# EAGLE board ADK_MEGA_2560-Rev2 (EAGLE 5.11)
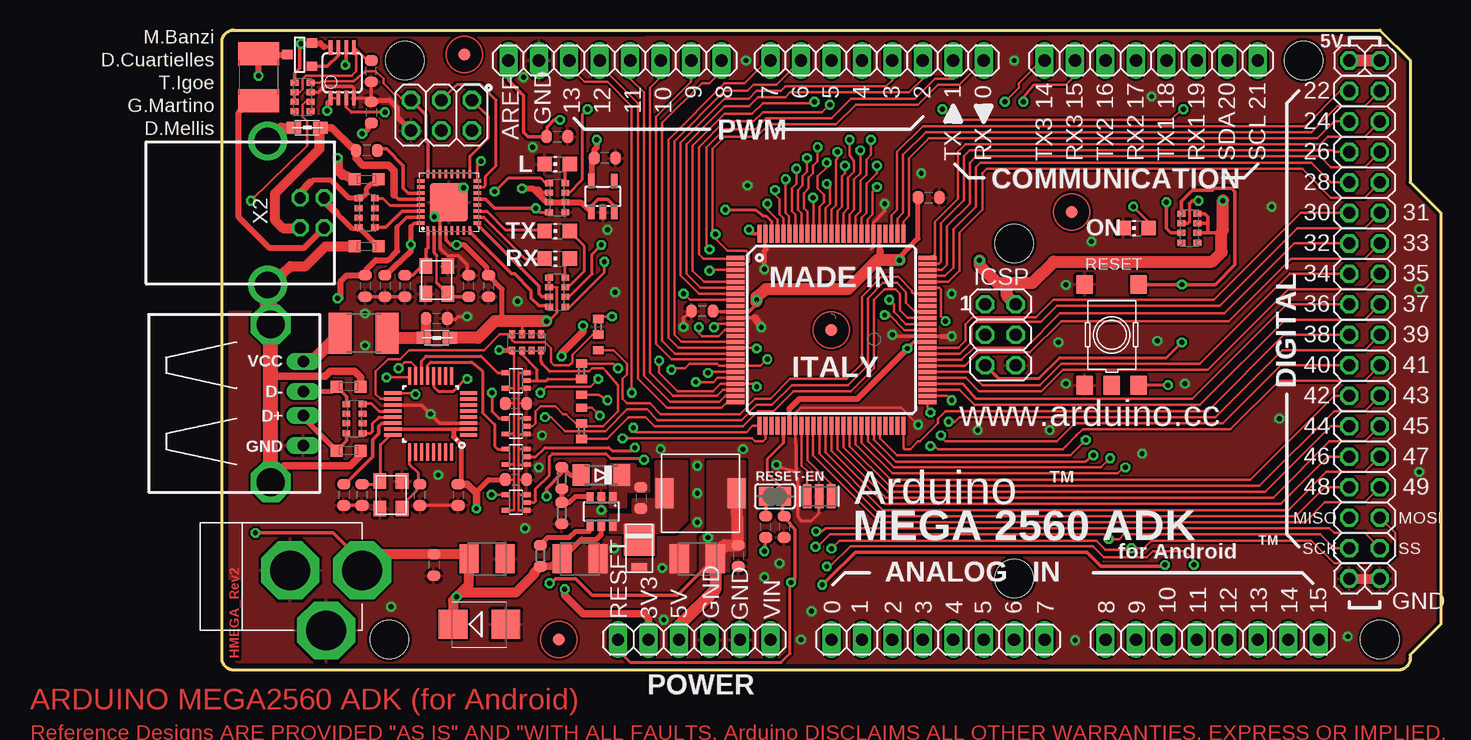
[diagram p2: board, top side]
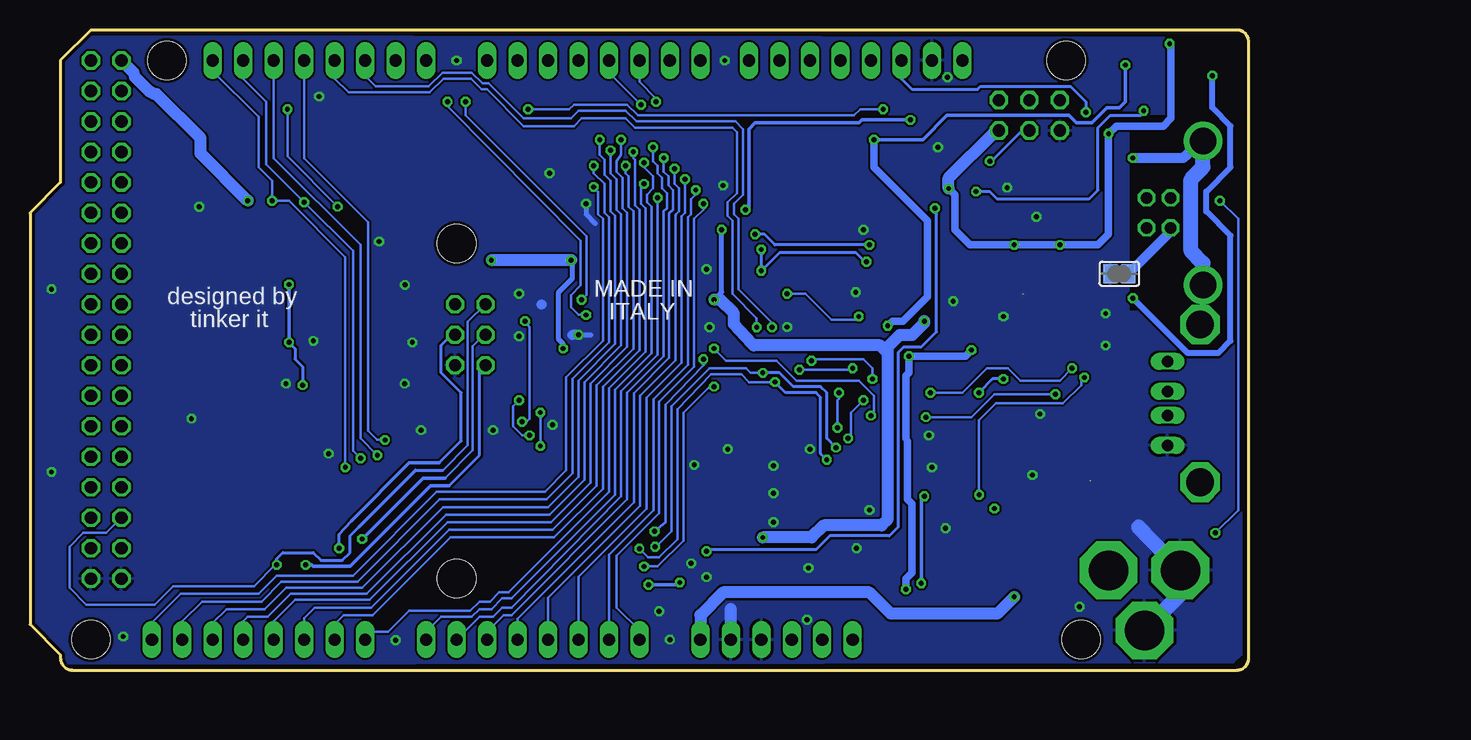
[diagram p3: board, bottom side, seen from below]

Size 101.6 x 53.34 mm. Coordinates in mm from the lower left corner, seen from the top.
Outline: 96.52,53.34 99.06,50.8 99.06,40.64 101.6,38.1 101.6,3.81 99.06,1.27 99.06,1 arc-90 98.06,0 1,0 arc-90 0,1 0,52.34 arc-90 1,53.34 96.52,53.34
Copper layers (1*16): Top 0.035mm / dielectric 1.5mm / Bottom 0.035mm
Design rules "ArduinoDEF": minimum track width 6mil, minimum drill 12mil, track to track 5mil, track to pad 5mil, pad to pad 5mil, via to via 5mil, smd to smd 4mil, copper to edge 10mil, drill to drill 6mil, minimum pad ring 8mil, minimum via ring 8mil, stop-mask expansion 0mil, vias tented up to drill 0mil, thermal gap 10mil
Net classes: 0 default: width 0.203 mm, drill 0.406 mm, clearance 0.178 mm; 1 power: width 0.305 mm, drill 0.406 mm, clearance 0.178 mm; 2 gnd: width 0.305 mm, drill 0.406 mm, clearance 0.178 mm; 3 power usb: width 0.508 mm, drill 0.406 mm, clearance 0.178 mm
Holes 3.2 mm at 96.52,2.54 15.24,50.8 90.17,50.8 13.97,2.54 66.04,35.56 66.04,7.62

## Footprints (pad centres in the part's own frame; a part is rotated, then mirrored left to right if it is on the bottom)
1X08 = drill 1.016 long: 1 -8.89,0; 2 -6.35,0; 3 -3.81,0; 4 -1.27,0; 5 1.27,0; 6 3.81,0; 7 6.35,0; 8 8.89,0
C0603-ROUND = smd 0.898 x 1.1: 1 -0.889,0; 2 0.889,0
SMC_B = smd 1.6 x 2.4: + -1.5,0; - 1.5,0
MINIMELF = smd 1.4 x 1.8: A 1.7,0; C -1.7,0
SMB = smd 2.4 x 2.4: A 2.2,0; C -2.2,0
DO220AAL = smd 2.667 x 2.54: P$1 -0.7,0 | smd 0.762 x 1.27: P$2 1.65,0
L1812 = smd 1.9 x 3.4: 1 -1.95,0; 2 1.95,0
SJ = smd 1.168 x 1.6: 1 -0.762,0; 2 0.762,0
MSOP08 = smd 0.3 x 1.2: 1 -0.976,-2.113; 2 -0.326,-2.113; 3 0.324,-2.113; 4 0.974,-2.113; 5 0.974,2.112; 6 0.324,2.112; 7 -0.326,2.112; 8 -0.976,2.112
SOT23-6 = smd 0.6 x 0.9: 1 -0.95,-1.15; 2 0,-1.15; 3 0.95,-1.15; 4 0.95,1.15; 5 0,1.15; 6 -0.95,1.15
TQFP100 = smd 1.5 x 0.35: 1 -8,6; 2 -8,5.5; 3 -8,5; 4 -8,4.5; 5 -8,4; 6 -8,3.5; 7 -8,3; 8 -8,2.5; 9 -8,2; 10 -8,1.5; 11 -8,1; 12 -8,0.5; 13 -8,0; 14 -8,-0.5; 15 -8,-1; 16 -8,-1.5; 17 -8,-2; 18 -8,-2.5; 19 -8,-3; 20 -8,-3.5; 21 -8,-4; 22 -8,-4.5; 23 -8,-5; 24 -8,-5.5; 25 -8,-6; 51 8,-6; 52 8,-5.5; 53 8,-5; 54 8,-4.5; 55 8,-4; 56 8,-3.5; 57 8,-3; 58 8,-2.5; 59 8,-2; 60 8,-1.5; 61 8,-1; 62 8,-0.5; 63 8,0; 64 8,0.5; 65 8,1; 66 8,1.5; 67 8,2; 68 8,2.5; 69 8,3; 70 8,3.5; 71 8,4; 72 8,4.5; 73 8,5; 74 8,5.5; 75 8,6 | smd 0.35 x 1.5: 26 -6,-8; 27 -5.5,-8; 28 -5,-8; 29 -4.5,-8; 30 -4,-8; 31 -3.5,-8; 32 -3,-8; 33 -2.5,-8; 34 -2,-8; 35 -1.5,-8; 36 -1,-8; 37 -0.5,-8; 38 0,-8; 39 0.5,-8; 40 1,-8; 41 1.5,-8; 42 2,-8; 43 2.5,-8; 44 3,-8; 45 3.5,-8; 46 4,-8; 47 4.5,-8; 48 5,-8; 49 5.5,-8; 50 6,-8; 76 6,8; 77 5.5,8; 78 5,8; 79 4.5,8; 80 4,8; 81 3.5,8; 82 3,8; 83 2.5,8; 84 2,8; 85 1.5,8; 86 1,8; 87 0.5,8; 88 0,8; 89 -0.5,8; 90 -1,8; 91 -1.5,8; 92 -2,8; 93 -2.5,8; 94 -3,8; 95 -3.5,8; 96 -4,8; 97 -4.5,8; 98 -5,8; 99 -5.5,8; 100 -6,8
ATMEL_QFN32 = smd 0.711 x 0.305: 1 -2.351,1.75; 2 -2.351,1.25; 3 -2.351,0.75; 4 -2.351,0.25; 5 -2.351,-0.25; 6 -2.351,-0.75; 7 -2.351,-1.25; 8 -2.351,-1.75; 17 2.351,-1.75; 18 2.351,-1.25; 19 2.351,-0.75; 20 2.351,-0.25; 21 2.351,0.25; 22 2.351,0.75; 23 2.351,1.25; 24 2.351,1.75 | smd 0.305 x 0.711: 9 -1.75,-2.351; 10 -1.25,-2.351; 11 -0.75,-2.351; 12 -0.25,-2.351; 13 0.25,-2.351; 14 0.75,-2.351; 15 1.25,-2.351; 16 1.75,-2.351; 25 1.75,2.351; 26 1.25,2.351; 27 0.75,2.351; 28 0.25,2.351; 29 -0.25,2.351; 30 -0.75,2.351; 31 -1.25,2.351; 32 -1.75,2.351 | smd 3.2 x 3.2: EXP 0,0
SC70-5 = smd 0.4 x 0.7: 1 -0.65,-0.85; 2 0,-0.85; 3 0.65,-0.85; 4 0.65,0.85; 5 -0.65,0.85
SOT23-DBV = smd 0.55 x 1.2: 1 -0.95,-1.3; 2 0,-1.3; 3 0.95,-1.3; 4 0.95,1.3; 5 -0.95,1.3
2X03 = drill 1.016 octagon: 1 -2.54,-1.27; 2 -2.54,1.27; 3 0,-1.27; 4 0,1.27; 5 2.54,-1.27; 6 2.54,1.27
1X01 = drill 1.016 octagon: 1 0,0
CHIP-LED0805 = smd 1.2 x 1.2: A 0,-1.05; C 0,1.05
SRR0604 = smd 1.5 x 2.5: P$1 3,0; P$2 -3,0
0805 = smd 1.2 x 1: 1 -1.1,0; 2 1.1,0
PN87520 = drill 0.95 long: 1 -3.5,2.71; 2 -1,2.71; 3 1,2.71; 4 3.5,2.71 | drill 2.3 octagon: SG1 -6.57,0; SG2 6.57,0
1X06 = drill 1.016 long: 1 -6.35,0; 2 -3.81,0; 3 -1.27,0; 4 1.27,0; 5 3.81,0; 6 6.35,0
R0603-ROUND = smd 0.898 x 1.1: 1 -0.889,0; 2 0.889,0
J0402 = smd 0.7 x 0.9: 1 -0.65,0; 2 0.65,0; 3 1.95,0
R0402 = smd 0.7 x 0.9: 1 -0.65,0; 2 0.65,0
TS42 = smd 1.6 x 1.4: 1 -4.2,2.25; 2 4.2,2.25; 3 -4.2,-2.25; 4 4.2,-2.25; 5 -4.2,0
CAT16 = smd 0.5 x 0.65: 1 -1.2,-0.675; 2 -0.4,-0.675; 3 0.4,-0.675; 4 1.2,-0.675; 5 1.2,0.675; 6 0.4,0.675; 7 -0.4,0.675; 8 -1.2,0.675
CAY16 = smd 0.5 x 0.65: 1 -1.2,-0.675; 2 -0.4,-0.675; 3 0.4,-0.675; 4 1.2,-0.675; 5 1.2,0.675; 6 0.4,0.675; 7 -0.4,0.675; 8 -1.2,0.675
SOT-23 = smd 0.787 x 0.889: 1 0.025,-1.016; 2 -0.94,1.016; 3 0.991,1.016
TQFP32-05 = smd 0.27 x 1.45: 1 -1.75,-3.16; 2 -1.25,-3.16; 3 -0.75,-3.16; 4 -0.25,-3.16; 5 0.25,-3.16; 6 0.75,-3.16; 7 1.25,-3.16; 8 1.75,-3.16; 17 1.75,3.16; 18 1.25,3.16; 19 0.75,3.16; 20 0.25,3.16; 21 -0.25,3.16; 22 -0.75,3.16; 23 -1.25,3.16; 24 -1.75,3.16 | smd 1.45 x 0.27: 9 3.16,-1.75; 10 3.16,-1.25; 11 3.16,-0.75; 12 3.16,-0.25; 13 3.16,0.25; 14 3.16,0.75; 15 3.16,1.25; 16 3.16,1.75; 25 -3.16,1.75; 26 -3.16,1.25; 27 -3.16,0.75; 28 -3.16,0.25; 29 -3.16,-0.25; 30 -3.16,-0.75; 31 -3.16,-1.25; 32 -3.16,-1.75
FIDUCIA-MOUNT = smd 1.016 x 1.016: P$1 0,0
DC-21MM = drill 3.302 pad 4.826 octagon: 1 -5.08,-3.353; 2 -0.076,-6.35; 3 -0.076,-0.356
PN61729 = drill 0.95 octagon: 1 1.25,4.71; 2 -1.25,4.71; 3 -1.25,2.71; 4 1.25,2.71 | drill 2.2 round: P$1 -6,0; P$2 6,0
2X08 = drill 1.016 octagon: 1 -8.89,-1.27; 2 -8.89,1.27; 3 -6.35,-1.27; 4 -6.35,1.27; 5 -3.81,-1.27; 6 -3.81,1.27; 7 -1.27,-1.27; 8 -1.27,1.27; 9 1.27,-1.27; 10 1.27,1.27; 11 3.81,-1.27; 12 3.81,1.27; 13 6.35,-1.27; 14 6.35,1.27; 15 8.89,-1.27; 16 8.89,1.27
RESONATOR = smd 0.7 x 2: 1 -1,0; 2 0,0; 3 1,0
CRYSTAL-3.2-2.5 = smd 1.3 x 1.05: 1 -1.15,-0.925; 2 1.15,-0.925; 3 1.15,0.925; 4 -1.15,0.925
CT/CN0603 = smd 1 x 1: 1 -1,0; 2 1,0

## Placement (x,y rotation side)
ADCH  [1X08]  82.55,2.54 0 top
ADCL  [1X08]  59.69,2.54 0 top
C1  22p  [C0603-ROUND]  46.86,11.94 270 top
C2  10n  [C0603-ROUND]  34.92,14.35 270 top
C3  100n  [C0603-ROUND]  17.65,8.76 270 top
C4  10u  [SMC_B]  29.84,9.27 0 top
C5  10u  [SMC_B]  39.62,9.27 180 top
C6  100n  [C0603-ROUND]  27.94,44.45 0 top
C7  100n  [C0603-ROUND]  43.05,9.53 270 top
C8  100n  [C0603-ROUND]  58.93,39.37 0 top
C9  100n  [C0603-ROUND]  40.05,29.91 180 top
C10  100n  [C0603-ROUND]  45.34,11.94 90 top
C11  100n  [C0603-ROUND]  11.94,32 270 top
C12  22p  [C0603-ROUND]  20.57,32 90 top
C13  22p  [C0603-ROUND]  15.24,32 270 top
C14  100n  [C0603-ROUND]  22.23,32 270 top
C15  100n  [C0603-ROUND]  13.59,32 270 top
C16  1u  [C0603-ROUND]  12.06,43.31 180 top
C17  100n  [C0603-ROUND]  17.91,29.31 0 top
C18  100n  [C0603-ROUND]  19.68,14.61 270 top
C19  22p  [C0603-ROUND]  16.51,14.61 90 top
C20  22p  [C0603-ROUND]  11.68,14.61 90 top
C21  100n  [C0603-ROUND]  12.45,46.48 270 top
C22  100n  [C0603-ROUND]  12.45,49.91 90 top
C23  1u  [C0603-ROUND]  31.93,42.67 180 top
C24  100n  [C0603-ROUND]  10.16,14.61 270 top
C25  100n  [C0603-ROUND]  24.51,22.23 0 top
C26  100n  [C0603-ROUND]  24.51,15.88 0 top
COMMUNICATION  [1X08]  77.47,50.8 180 top
D1  4148  [MINIMELF]  31.62,16.26 180 top
D2  M7  [SMB]  21.46,3.81 0 top
D3  SS1P3L  [DO220AAL]  34.8,10.16 270 top
F1  500mA  [L1812]  3.05,49.4 270 top
F2  500mA  [L1812]  11.81,28.07 180 top
GROUND  [SJ]  10.79,33.02 180 bottom
IC1  LMV358MMX  [MSOP08]  10.03,49.78 0 top
IC2  LM2736Y  [SOT23-6]  31.62,13.21 180 top
IC3  ATMEGA2560-16AU  [TQFP100]  50.8,28.35 0 top
IC4  ATMEGA8U2-MU  [ATMEL_QFN32]  18.92,38.99 90 top
IC5  74LVC1G125DCK  [SC70-5]  24.51,20.32 90 top
IC6  74LVC1G125DCK  [SC70-5]  24.51,17.78 90 top
IC7  LP2985-33DBVR  [SOT23-DBV]  31.75,39.47 0 top
IC8  74LVC1G125DCK  [SC70-5]  24.51,24.13 90 top
IC9  74LVC1G125DCK  [SC70-5]  24.51,13.97 90 top
ICSP  ICSP  [2X03]  64.9,27.94 270 top
ICSP1  ICSP  [2X03]  18.29,46.23 180 top
JP1  [1X01]  93.98,50.8 0 top
JP2  [1X01]  96.52,50.8 0 top
JP3  [1X01]  93.98,7.62 0 top
JP4  [1X01]  96.52,7.62 0 top
L  YELLOW  [CHIP-LED0805]  27.94,42.16 90 top
L1  4u7  [SRR0604]  39.88,14.73 180 top
L2  BLM21  [0805]  7.11,45.21 180 top
L3  BLM21  [0805]  17.91,27.69 180 top
ON  GREEN  [CHIP-LED0805]  76.2,36.83 90 top
PC1  47u  [SMC_B]  22.1,9.27 0 top
PHONE  [PN87520]  4.06,22.23 270 top
POWER  [1X06]  39.37,2.54 0 top
PWMH  [1X08]  32.77,50.8 180 top
PWML  [1X08]  54.61,50.8 180 top
R1  100k  [R0603-ROUND]  26.54,9.53 90 top
R2  10k  [R0603-ROUND]  28.32,16 270 top
R3  3k3  [R0603-ROUND]  28.32,13.08 270 top
R4  NM  [J0402]  29.97,21.21 270 top
R5  0R  [R0402]  29.97,24.89 90 top
R6  0R  [R0402]  29.97,19.91 90 top
R7  NM  [J0402]  29.97,23.6 90 top
R8  NM  [J0402]  31.37,27.3 90 top
R9  0R  [R0402]  31.37,28.57 90 top
RESET  TS42  [TS42]  74.17,27.94 90 top
RESET-EN  [SJ]  46.1,14.48 180 top
RN1  10K  [CAT16]  80.64,36.83 270 top
RN2  1k  [CAY16]  27.94,39.37 270 top
RN3  10K  [CAT16]  6.73,47.75 270 top
RN4  22R  [CAY16]  12.06,38.1 90 top
RN5  1k  [CAY16]  27.94,31.5 90 top
RN6  10K  [CAT16]  25.4,27.3 0 top
RN7  22R  [CAY16]  11.05,20.95 270 top
RX  YELLOW  [CHIP-LED0805]  27.94,34.29 90 top
T1  FDN340P  [SOT-23]  6.48,51.31 270 top
TX  YELLOW  [CHIP-LED0805]  27.94,36.58 90 top
U7A  MAX3421EEHJ  [TQFP32-05]  17.4,21.34 90 top
U$1  FIDUCIALMOUNT  [FIDUCIA-MOUNT]  70.84,38.19 0 top
U$2  FIDUCIALMOUNT  [FIDUCIA-MOUNT]  28.07,2.54 0 top
U$3  FIDUCIALMOUNT  [FIDUCIA-MOUNT]  50.8,28.35 0 top
U$4  FIDUCIALMOUNT  [FIDUCIA-MOUNT]  20.19,51.31 0 top
X1  DC21MMX  [DC-21MM]  5.33,8.38 90 top
X2  [PN61729]  3.81,38.1 270 top
XIOH  [2X08]  95.25,39.37 90 top
XIOL  [2X08]  95.25,19.05 90 top
Y1  16MHz  [RESONATOR]  49.78,14.48 0 top
Y2  16MHz KX-7  [CRYSTAL-3.2-2.5]  17.91,32.51 270 top
Y3  12MHz KX-7  [CRYSTAL-3.2-2.5]  14.1,14.61 270 top
Z1  PGB1010604  [CT/CN0603]  12.06,35.31 0 top
Z2  PGB1010604  [CT/CN0603]  12.06,40.89 0 top
Z3  PGB1010604  [CT/CN0603]  10.54,18.29 180 top
Z4  PGB1010604  [CT/CN0603]  10.54,23.62 180 top

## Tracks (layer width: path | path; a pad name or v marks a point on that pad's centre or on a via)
+3V3  (via drill 0.41)
  Top 0.203: 24.33,22.23 C25.1 | 24.33,22.23 24.33,23.48 | 24.33,23.48 IC8.5 | C26.1 24.33,15.88 | IC9.5 24.33,13.32 24.33,15.88 | RN6.1 24.2,26.35 24.33,26.21 24.33,23.48 | 24.33,15.88 24.33,17.14 | 24.33,17.14 24.33,19.68 | 24.33,19.68 24.33,22.23 | IC5.5 23.68,19.68 24.33,19.68 | IC6.5 23.68,17.14 24.33,17.14
  Top 0.305: IC1.6 10.36,50.67 v10.29,50.42 | U7A.23 19.3,20.09 | 19.3,20.09 U7A.2 | 19.3,20.09 19.3,19.96
  Top 0.406: C18.1 19.94,15.75 19.94,18.8 19.3,19.43 19.3,19.96 | C26.1 22.23,15.88 21.21,14.86 | v23.11,26.67 23.15,26.63 RN6.1
  Top 0.508: v31.24,44.2 31.24,43.54 31.04,43.33 C23.2 30.8,42.69 IC7.5
  Top 0.61: 21.21,14.73 v21.21,13.46 | 21.21,14.73 21.21,14.86 | C18.1 20.45,15.49 21.21,14.73 | v28.32,26.16 28.32,26.42 30.1,28.19 v30.1,28.7 | POWER.2 35.56,4.32 35.18,4.7 30.1,4.7 28.57,6.22 v28.57,6.73
  Bottom 0.305: v10.29,50.42 10.29,47.37 10.79,46.86 11.81,46.86 13.08,45.59 14.35,45.59 14.99,46.23 25.15,46.23 27.18,44.2 v31.24,44.2
  Bottom 0.61: v23.11,26.67 23.62,26.16 v28.32,26.16 28.32,24.77 28.57,24.51 28.57,19.3 28.45,19.05 28.45,14.22 28.07,13.84 28.07,8.13 28.57,7.62 v28.57,6.73 | v30.1,28.7 29.72,29.08 28.83,29.08 26.8,31.11 26.8,37.47 31.24,41.91 v31.24,44.2
+5V  (via drill 0.41)  (1 unrouted)
  Top 0.203: T1.2 6.78,52.25 | IC7.1 30.81,38.31
  Top 0.254: IC3.80 54.81,36.3 54.79,36.27 54.81,36.25 54.81,35.41 | 57.66,27.3 57.7,27.35 | v27.05,29.08 27.24,29.08 27.94,29.78 27.94,31.88 27.41,31.9 RN5.6 RN5.5 | RN6.7 25,28.81 25.27,29.08
  Top 0.305: 54.86,34.92 54.86,35.1 54.81,35.15 54.81,35.41 | 57.7,27.35 IC3.61 | v57.15,26.8 57.66,27.3 | IC3.100 44.17,36.35 v43.94,36.7 | RN1.8 81.92,38.03 82.17,37.78 82.17,37.21 | 83.31,36.45 82.17,36.45 | RN1.6 82.15,36.43 82.17,36.45 | 82.17,36.45 82.17,37.21 | RN1.7 82.15,37.23 82.17,37.21 | C9.1 41.59,29.85 IC3.10 43.94,29.85 44.58,30.48 v44.58,30.86 | 6.78,52.25 6.48,51.94 6.48,50.16 6.06,49.74 RN3.1 | 8.51,51.94 9.01,51.94 IC1.8 | IC4.32 16.03,37.24 15.75,36.96 | IC4.4 18.67,35.81 19.05,35.43 v19.56,35.43 | IC7.3 32.7,38.67 32.13,39.24 31.37,39.24 30.81,38.68 30.81,38.31 | RN2.2 26.78,39.77 26.42,40.13 25.91,40.13 | C5.+ 40.74,8.99 37.97,6.22 30.86,6.22 29.46,7.62 27.81,7.62 27.43,7.24 v27.3,7.24 | v27.05,14.48 27.05,15.11 28.32,16.38 R2.1
  Top 0.356: IC3.31 47.3,21.77
  Top 0.406: 44.55,30.7 44.45,30.48 | C8.1 58.04,35.97 56.52,34.42 56.49,34.39 v56.49,34.16 | v11.68,44.7 11.81,44.7 12.19,45.09 12.19,45.34 C21.2 | 15.75,34.92 v15.75,35.43 15.75,36.96 | v19.56,35.43 20.19,35.43 22.1,33.53 22.1,32.89 C14.1 23.37,31.75 23.37,29.08 | D1.A 29.08,16.26 R2.1
  Top 0.508: 47.3,21.77 48.13,22.61 52.96,22.61 v57.15,26.8 | v6.6,52.2 T1.2 8.2,52.25 8.51,51.94 | IC7.1 29.88,38.97 RN2.6 RN2.3 27.07,38.97 25.91,40.13 v25.02,40.13 | 15.75,34.92 C15.1
  Top 0.61: 54.86,34.29 54.86,34.92
  Top 0.813: 83.31,34.8 83.31,34.92
  Top 1.016: POWER.3 38.1,3.68 41.12,6.71 C5.+ | JP1.1 JP2.1 | 65.41,32.26 64.64,32.26 63.14,33.76 v63.14,34.14 | 83.31,34.92 83.31,36.45 83.44,36.7 v83.44,39.12 | 44.55,30.7 44.55,31.08 45.34,31.75 52.2,31.75 54.61,34.16 54.99,34.16 | 65.41,32.26 65.41,31.24 ICSP.2 | 65.41,32.26 67.56,32.26 69.34,34.04 82.55,34.04 83.31,34.8 | v56.49,34.16 54.99,34.16 | 54.99,34.16 54.86,34.29 | L3.1 21.34,27.69 22.73,29.08 23.37,29.08 25.27,29.08 v27.05,29.08 | 41.25,10.06 41.38,9.76 41.91,10.41 C7.1 43.01,10.97 L1.P$2
  Bottom 0.305: v27.3,7.24 27.3,14.35 v27.05,14.48
  Bottom 0.406: v44.58,30.86 44.58,30.73 43.94,31.5 v43.94,36.7 | v57.15,26.8 57.15,27.18 57.53,27.56 57.53,31.5 56.39,32.64 56.39,34.06 v56.49,34.16 56.77,34.16
  Bottom 0.61: 63.12,34.16 v63.14,34.14 | v25.02,40.13 24.49,39.6 24.49,36.68 23.24,35.43 v19.56,35.43 v15.75,35.43 12.57,35.43 11.68,36.32 v11.68,44.7 11.05,45.34 7.11,45.34 6.48,45.97 6.48,52.07 v6.6,52.2
  Bottom 1.016: POWER.3 38.1,3.43 | v56.49,34.16 63.12,34.16 | v44.58,30.86 44.07,30.86 42.93,29.72 42.93,28.83 41.4,27.18 41.27,27.05 30.73,27.05 30.1,26.42 | ICSP1.2 20.95,44.83 21.21,44.83 25.02,41.02 v25.02,40.13 | v83.44,39.12 87.38,43.05 87.38,44.32 91.06,48.01 91.19,48.01 91.69,48.26 92.84,49.4 92.96,49.78 JP1.1 | 30.1,26.42 30.1,26.94 29.1,27.94 28.05,27.94 27.05,28.94 v27.05,29.08 | 30.1,26.42 30.1,12.57 30.61,12.06 35.43,12.06 36.45,11.05 v40.51,11.05
  pour Top (no thermals): 40.51,17.4 43.56,17.4 43.56,9.53 42.29,9.53 42.29,8.26 39.88,8.26 39.88,11.05 40.51,11.68
ADC0  (via drill 0.41)
  Top 0.203: IC3.97 46.3,37.52 45.47,38.35 v45.47,38.86
  Bottom 0.203: ADCL.1 50.8,3.3 52.7,5.21 52.7,9.53 49.15,13.08 49.15,22.35 46.23,25.27 46.23,37.59 45.47,38.35 v45.47,38.86
ADC1  (via drill 0.41)
  Top 0.203: IC3.96 46.8,37.66 46.48,37.97 46.48,39.24 46.1,39.62 v46.1,40.01
  Bottom 0.203: ADCL.2 53.34,9.6 49.63,13.31 49.63,22.55 46.74,25.45 46.74,37.72 46.48,37.97 46.48,39.24 46.1,39.62 v46.1,40.01
ADC2  (via drill 0.41)
  Top 0.203: v46.99,40.89 46.99,38.1 47.27,37.82 47.27,36.68 47.37,36.58 47.3,36.51 47.3,36.38 47.27,36.35 | 47.27,36.35 47.24,36.32 | 47.27,36.35 IC3.95
  Bottom 0.203: ADCL.3 55.88,7.8 50.22,13.46 50.22,22.68 47.27,25.63 47.27,37.82 46.99,38.1 v46.99,40.89
ADC3  (via drill 0.41)
  Top 0.203: IC3.94 47.8,37.92 47.5,38.23 47.5,40.13 47.88,40.51 v47.88,41.78
  Bottom 0.203: ADCL.4 58.42,2.74 58.52,2.85 58.52,3.05 58.42,3.15 58.42,6.02 50.75,13.69 50.75,22.86 47.8,25.81 47.8,37.85 47.75,37.97 47.5,38.23 47.5,40.13 47.88,40.51 v47.88,41.78
ADC4  (via drill 0.41)
  Top 0.203: IC3.93 48.3,38.06 48.01,38.35 48.01,40.01 48.39,40.39 48.39,41.15 48.77,41.53 v48.77,42.67
  Bottom 0.203: 60.96,2.44 ADCL.5 60.96,4.27 51.26,13.97 51.26,23.06 48.31,26.01 48.31,38.05 48.01,38.35 48.01,40.01 48.39,40.39 48.39,41.15 48.77,41.53 v48.77,42.67
ADC5  (via drill 0.41)
  Top 0.203: IC3.92 48.8,38.2 48.51,38.48 48.51,39.75 48.9,40.13 48.9,41.02 49.28,41.4 49.28,42.04 49.66,42.42 v49.66,43.56
  Bottom 0.203: v49.66,43.56 49.66,42.42 49.28,42.04 49.28,41.4 48.9,41.02 48.9,40.13 48.51,39.75 48.51,38.48 48.77,38.23 48.77,26.16 51.82,23.11 51.82,14.22 61.47,4.57 62.1,4.57 63.5,3.17 ADCL.6
ADC6  (via drill 0.41)
  Top 0.203: IC3.91 49.3,39.35 v49.28,39.37
  Bottom 0.203: v49.28,39.37 49.28,26.29 52.32,23.24 52.32,14.48 61.47,5.21 62.23,5.21 62.99,4.45 64.14,4.45 ADCL.7
ADC7  (via drill 0.41)
  Top 0.203: IC3.90 49.8,38.62 50.16,38.99 50.16,39.62 49.66,40.13 49.66,41.15 50.42,41.91 v50.42,42.29
  Bottom 0.203: v50.42,42.29 50.42,41.91 49.66,41.15 49.66,40.13 50.16,39.62 50.16,38.99 49.78,38.61 49.78,26.42 52.83,23.37 52.83,14.61 61.47,5.97 62.23,5.97 63.12,5.08 64.14,5.08 64.77,4.45 67.31,4.45 68.58,3.17 ADCL.8
ADC8  (via drill 0.41)
  Top 0.203: IC3.89 50.3,38.49 50.67,38.86 50.67,40.26 v50.42,40.51
  Bottom 0.203: v50.42,40.51 50.67,40.26 50.67,38.86 50.29,38.48 50.29,26.54 53.34,23.5 53.34,14.86 61.72,6.48 62.48,6.48 63.25,5.71 64.14,5.71 64.9,4.95 69.98,4.95 71.75,3.17 73.66,3.17 ADCH.1
ADC9  (via drill 0.41)
  Top 0.203: IC3.88 50.8,38.35 51.18,38.73 51.18,42.55 51.31,42.67 v51.31,43.18
  Bottom 0.203: v51.31,43.18 51.31,42.67 51.18,42.55 51.18,38.73 50.8,38.35 50.8,26.67 53.85,23.62 53.85,15.11 57.91,11.05 66.55,11.05 73.03,4.57 75.44,4.57 76.2,3.81 ADCH.2
ADC10  (via drill 0.41)
  Top 0.203: IC3.87 51.3,38.22 51.69,38.61 51.69,41.15 51.94,41.4 v51.94,42.04
  Bottom 0.203: v51.94,42.04 51.94,41.4 51.69,41.15 51.69,38.61 51.31,38.23 51.31,26.8 54.36,23.75 54.36,15.37 58.04,11.68 66.67,11.68 73.15,5.21 77.85,5.21 78.74,4.32 ADCH.3
ADC11  (via drill 0.41)
  Top 0.203: IC3.86 51.8,38.08 52.2,38.48 52.2,41.02 52.7,41.53 52.7,42.42 52.32,42.93 v52.32,44.2
  Bottom 0.203: v52.32,44.2 52.32,42.93 52.7,42.42 52.7,41.53 52.2,41.02 52.2,38.48 51.82,38.1 51.82,26.92 54.86,23.88 54.86,15.62 58.17,12.32 66.8,12.32 73.28,5.84 79.5,5.84 81.28,4.06 ADCH.4
ADC12  (via drill 0.41)
  Top 0.203: IC3.85 52.3,37.95 52.7,38.35 52.7,40.89 53.21,41.4 v53.21,43.31
  Bottom 0.203: v53.21,43.31 53.21,41.4 52.7,40.89 52.7,38.35 52.32,37.97 52.32,27.05 55.37,24 55.37,15.88 58.29,12.95 66.93,12.95 73.53,6.35 79.88,6.35 81.79,4.45 83.44,4.45 83.82,4.06 ADCH.5
ADC13  (via drill 0.41)
  Top 0.203: IC3.84 52.8,37.81 53.21,38.23 53.21,40.77 53.72,41.27 53.72,42.55 54.1,42.93 v54.1,44.2
  Bottom 0.203: v54.1,44.2 54.1,42.93 53.72,42.55 53.72,41.27 53.21,40.77 53.21,38.23 52.83,37.85 52.83,27.18 55.88,24.13 55.88,16.13 58.42,13.59 67.18,13.59 73.91,6.86 80.26,6.86 82.04,5.08 85.22,5.08 86.36,3.94 ADCH.6
ADC14  (via drill 0.41)
  Top 0.203: IC3.83 53.3,37.68 53.72,38.1 53.72,40.51 54.61,41.4 v54.61,42.04
  Bottom 0.203: v54.61,42.04 54.61,41.4 53.72,40.51 53.72,38.1 53.34,37.72 53.34,27.3 56.39,24.26 56.39,16.38 58.55,14.22 67.44,14.22 74.3,7.37 80.64,7.37 82.3,5.71 87.25,5.71 88.9,4.06 ADCH.7
ADC15  (via drill 0.41)
  Top 0.203: IC3.82 53.8,37.54 54.23,37.97 54.23,39.88 v54.61,40.26
  Bottom 0.203: v54.61,40.26 54.23,39.88 54.23,37.97 53.85,37.59 53.85,27.43 56.9,24.38 56.9,16.64 58.67,14.86 67.69,14.86 74.68,7.87 81.03,7.87 82.55,6.35 89.03,6.35 91.44,3.94 ADCH.8
AREF  (via drill 0.41)
  Top 0.254: IC3.98 45.8,37.38 45.34,37.85 45.09,37.85 44.45,38.35 v41.96,38.35
  Top 0.305: v28.19,45.85 27.69,45.85 27.09,45.25 27.09,45.09 C6.1 25.53,44.45 25.15,44.83 25.15,47.88 23.88,49.15 PWMH.8
  Bottom 0.305: v28.19,45.85 32.26,45.85 32.51,45.59 41.15,45.59 41.66,45.09 41.66,38.53 41.83,38.35 v41.96,38.35
BOOST
  pour Top (no thermals): 32.38,13.59 32.38,17.14 34.42,17.14 34.42,16.76 35.56,16.76 35.56,14.86 33.66,14.86 33.66,13.59
CMP
  Top 0.203: RN3.3 RN3.2 6.48,48.15 6.73,48.41 6.73,49.28 6.99,49.53 10.79,49.53 11.18,49.91 11.18,51.73 IC1.5 11.01,51.56
  Top 0.254: C22.2 12.1,50.8 IC1.5
D+
  Top 0.406: 7.37,40.64 7.58,40.85 9.06,40.85 10.54,39.37 11.32,39.37 RN4.5 11.61,39.3 12.06,39.75 12.06,40.13 12.45,40.51 12.94,40.51 Z2.2
  Top 0.61: X2.3 6.52,39.79 7.37,40.64
D-
  Top 0.406: 9.53,38.1 9.56,38.1 10.03,37.63 10.03,37.59 10.79,36.83 11.32,36.83 RN4.8 12.73,35.56 Z1.2
  Top 0.61: X2.2 8.53,39.1 9.53,38.1
DTR  (via drill 0.41)
  Top 0.254: RN2.4 26.47,38.17 v26.16,38.48
  Top 0.305: IC4.13 21.98,39.24 22.73,38.48 v26.16,38.48 | v45.21,9.91 C10.1
  Bottom 0.254: v45.21,9.91 44.96,9.91 44.83,10.03 36.07,10.03 34.92,11.18 29.97,11.18 29.21,11.94 29.21,26.48 28.77,26.92 27.3,26.92 26.04,28.19 26.04,37.97 26.16,38.1 v26.16,38.48
EN
  Top 0.406: IC2.4 30.67,11.62 30.61,11.56 29.46,11.56 28.96,11.05 27.18,11.05 R1.2
FB
  Top 0.406: R2.2 R3.1 28.96,13.97 29.46,14.48 30.55,14.48 IC2.3
GATE_CMD
  Top 0.305: IC1.7 9.71,51.24 8.79,50.32 T1.3
GND  (via drill 0.41)
  Top 0.203: IC8.3 24.71,24.78 24.71,23.48 | 24.71,23.48 IC8.1 | 24.71,22.23 24.71,23.48 | 24.71,22.23 C25.2 | IC5.3 24.78,20.97 24.71,20.95 | 24.71,20.95 24.71,22.23 | IC5.1 24.83,19.67 24.71,19.56 | 24.71,19.56 24.71,20.95 | IC6.3 25.35,18.41 24.71,18.41 | 24.71,18.41 24.71,19.56 | IC6.1 24.83,17.13 24.71,17.02 | 24.71,17.02 24.71,18.41 | 24.71,15.88 C26.2 | 24.71,15.88 24.71,17.02 | IC9.1 24.71,13.32 24.71,14.62 | 24.71,14.62 24.71,15.88 | IC9.3 24.71,14.62 | v58.04,20.45 56.64,21.84 48.26,21.84 47.8,21.39 IC3.32 | IC3.32 | 47.8,18.97 IC3.32 | 54.3,37.28 54.3,36.38 54.33,36.35 | 54.33,36.35 54.36,36.32 | 54.33,36.35 IC3.81 54.3,35.25 54.1,35.05
  Top 0.254: v46.23,17.1 46.4,16.89 47.88,16.51 | 47.8,18.97 47.88,18.67 47.88,16.51 | Y1.2 49.78,13.08 49.15,12.45 48.26,12.45 48.01,12.83 48.01,16 47.88,16.13 47.88,16.51
  Top 0.305: C24.2 C20.1 | C19.1 C18.2 | U7A.3 18.15,20.59 v17.4,21.34 16.65,22.09 U7A.19 | C13.2 C15.2 C11.2 | v20.45,29.46 19.68,29.46 19.43,29.21 C17.2 | IC4.EXP 18.8,37.85 v17.7,37.77 18.17,37.5 IC4.3 18.17,35.17 18.8,34.54 19.68,34.54 20.45,33.78 20.45,33.27 C12.2 | C22.1 C21.1 12.24,47.67 IC1.4 11.01,48.43 10.79,48.64 8.51,48.64 8.02,48.15 RN3.7 | v38.48,28.59 38.48,29.36 C9.2 | 44.42,29.36 44.35,29.36 44.32,29.34 44.32,29.36 | 44.32,29.36 44.4,29.36 | 44.32,29.36 42.88,29.36 42.86,29.35 IC3.11 | IC3.99 45.29,35.2 45.39,35.1 | 58.83,27.84 58.82,27.85 IC3.62 58.81,27.84 | 59.94,27.81 59.92,27.84 58.81,27.84 | 56.06,27.86 56.08,27.84 58.81,27.84 | v55.24,38.86 55.24,38.23 54.3,37.28
  Top 0.406: ICSP1.6 14.61,46.1 14.61,46.86 13.97,47.5 13.08,47.5 12.95,47.37 C21.1 | 45.39,35.1 45.21,34.92 v45.21,33.4 | 59.94,27.81 v60.83,27.81 | v55.88,27.94 56.01,27.81 56.06,27.86
  Top 0.61: 44.42,29.36 v44.96,28.57 | v55.88,27.94 55.88,27.81
  Top 0.813: JP3.1 JP4.1
  Bottom 0.305: GROUND.2 10.16,33.02
  Bottom 0.406: v55.88,27.94 54.86,27.94 | 54.48,37.21 55.24,37.97 v55.24,38.86
  Bottom 0.813: v55.88,27.94 56.39,27.94 | 58.98,30.48 58.93,30.48 | 93.73,7.87 JP3.1
  Bottom 1.016: POWER.5 43.18,5.08
  Bottom 1.27: 9.2,11.94 X1.3 5.69,6.3 X1.1
  other vias: 25.27,11.81 14.11,5.28 18.03,16.26 11.94,27.05 11.94,29.72 36.83,4.19 26.42,16.89 32.69,10.16 31.62,13.34 36.7,8.51 39.62,12.32 39.62,14.73 45.21,7.75 49.15,4.91 48.26,2.54 24.64,30.73 39.62,17.02 36.58,18.41 46.48,8.89 20.14,40.21 43.43,18.41 32.77,31.5 32.13,36.7 25.91,43.56 25.13,49.4 71.12,2.49 63,20 43.81,40.39 69,20 60.83,31.37 70.36,23.88 76.71,18.04 43.69,50.8 69.72,27.3 58.29,41.4 70.34,32.1 77.98,27.43 80.26,23.88 72.49,35.71 88.14,20.95 99.81,16.51 66.04,50.8 77.5,47.8 87.5,38.61 99.81,31.75 26.67,19.56 93.84,2.79
  pour Top (rank 2): 102.62,52.83 102.62,0.51 1.63,0.63 arc-90 0.64,1.63 0.64,29.84 9.91,29.84 9.91,46.35 0.64,46.35 0.64,51.71 arc-90 1.63,52.71
  pour Bottom (rank 2): 103.63,52.83 103.63,0.51 1.27,0.64 0.64,1.27 0.64,29.84 10.03,29.84 10.03,46.35 0.64,46.35 0.64,51.71 arc-90 1.63,52.71
  pour Top (no thermals): 33.02,10.79 33.02,9.02 36.58,9.02 36.58,10.79 39.24,10.79 39.24,8.26 38.48,7.49 30.35,7.49 30.1,7.75 30.1,10.03 30.35,10.29 31.5,10.29 32,10.79
GPX_MAX  (via drill 0.41)
  Top 0.203: IC3.66 57.78,29.85 57.02,30.61 57.02,31.5 56.26,32.26 55.12,32.26 53.85,30.99 53.85,25.4 52.2,23.75 47.5,23.75 45.85,22.1 44.58,22.1 43.31,20.83 36.32,20.83 35.43,21.72 33.78,21.72 31.98,19.91 28.58,19.91 27.42,21.08 v26.92,21.08 | v16.13,22.99 16.03,23.09 U7A.17
  Bottom 0.203: v26.92,21.08 23.11,21.08 21.21,22.99 v16.13,22.99
INT_MAX
  Top 0.203: R8.2 30.88,27.95 29.21,26.29 29.21,25.65 28.96,25.4 27.69,25.4 27.43,25.65 27.43,26.82 26.95,27.3 24.38,27.3 24.2,27.5 RN6.8 23.15,27.98 21.84,26.67 15.62,26.67 14.86,25.91 13.84,25.91 12.83,24.89 12.83,22.99 13.21,22.61 14.22,22.61 U7A.18
M8RXD
  Top 0.254: RN5.7 27.25,31.11
  Top 0.305: 27.25,31.11 26.67,31.11 26.42,31.37 26.42,32 21.27,37.15 IC4.9
M8TXD
  Top 0.305: RN5.8 27.21,30.35 26.42,30.35 25.78,30.99 25.78,31.62 24.38,33.02 24.13,33.02 20.67,36.48 IC4.8
MISO2
  Top 0.254: IC4.17 20.68,41.4 20.68,42.82 22.23,44.37 22.23,46.1 ICSP1.1
MOSI2  (via drill 0.41)
  Top 0.254: IC4.16 21.27,40.89 21.27,42.1 v21.59,42.42
  Bottom 0.254: ICSP1.4 18.92,44.96 21.46,42.42 v21.59,42.42
MOSI_3V3  (via drill 0.41)
  Top 0.203: IC9.4 22.72,14.62 v22.48,14.61 | v13.72,24.38 15.54,24.38 U7A.16
  Bottom 0.203: v22.48,14.61 22.48,20.83 21.08,22.23 15.49,22.23 13.97,23.75 13.97,24.13 v13.72,24.38
N$1  (via drill 0.41)
  Top 0.203: IC1.1 IC1.2
  Top 0.254: v8.76,46.61 8.76,47.38 IC1.1 | RN2.1 26.99,40.57 26.54,41.02 23.88,41.02 v22.73,39.88
  Bottom 0.254: v22.73,39.88 21.59,39.88 20.95,39.24 13.34,39.24 12.57,40.01 12.57,45.21 11.56,46.23 9.02,46.23 v8.76,46.61
N$2
  Top 0.305: RN2.8 28.61,41.79 L.A
N$3  (via drill 0.41)
  Top 0.203: 77.22,37.08 ON.A | v80.14,46.74 80.01,46.74 79.12,45.85 60.96,45.85 v60.07,46.74
  Top 0.254: RN2.7 28.89,39.75 28.96,39.75 30.05,40.89 30.05,46.3 v30.48,46.74 | 77.22,37.08 77.22,37.37 v75.96,38.62
  Bottom 0.203: v80.14,46.74 80.14,42.8 v75.96,38.62 | v60.07,46.74 56.64,46.74 56.26,47.12 51.82,47.12 50.93,46.23 32.89,46.23 32.38,46.74 v30.48,46.74
N$10
  Top 0.305: RN7.1 10.37,22.79 Z4.2
  Top 0.406: PHONE.2 9.14,23.23 Z4.2
N$11
  Top 0.305: RN7.4 10.37,19.12 Z3.2
  Top 0.406: PHONE.3 6.6,21.23 Z3.2
N$12
  Top 0.254: U7A.20 13.09,21.59 12.45,22.23 11.79,22.23 RN7.8
N$13
  Top 0.254: U7A.21 13.09,21.09 12.57,20.57 12.57,19.94 12.39,19.75 RN7.5
N$14
  Top 1.016: PHONE.1 7.52,25.73 F2.2
N$15  (1 unrouted)
  Top 0.254: C20.2 12.94,15.49 | U7A.24 14,19.59 13.21,18.8 13.21,15.77
  Top 0.305: 12.94,15.49 12.94,15.52 Y3.1
N$16
  Top 0.254: U7A.25 15.65,17.12 16.38,16.38 16.38,15.62 C19.2 16.26,15.24 16.26,14.99 15,13.73 15,13.48
  Top 0.305: Y3.3 15,13.48
N$18
  Top 0.813: 17.02,27.77 C17.1
  Top 1.016: F2.1 14.27,27.69 L3.2 17.02,27.77
N$39
  Top 0.305: U7A.22 13.35,20.59 13.08,20.32 13.08,19.68 12.57,19.18 12.57,17.78 10.41,15.62 10.29,15.49 C24.1
N$54
  Top 0.254: RN5.4 28.61,33.82 RX.A
N$55
  Top 0.254: RN5.3 28.85,31.9 30.23,33.27 30.23,35.31 TX.A
PA0
  Top 0.203: IC3.78 55.8,37.89 56.26,38.35 56.26,43.18 58.42,45.34 90.3,45.34 93.22,48.26 XIOH.16
PA1
  Top 0.203: IC3.77 56.3,37.63 56.77,38.1 56.77,42.93 58.67,44.83 90.81,44.83 92.96,46.99 95.25,46.99 XIOH.15
PA2
  Top 0.203: XIOH.14 92.71,45.72 91.31,44.32 58.93,44.32 57.28,42.67 57.28,37.85 56.8,37.37 IC3.76
PA3
  Top 0.203: XIOH.13 95.25,44.45 92.2,44.45 91.57,43.81 61.98,43.81 61.34,43.18 61.34,39.26 59.44,37.35 59.44,34.67 59.11,34.35 IC3.75
PA4
  Top 0.203: IC3.74 59.75,33.85 59.94,34.04 59.94,37.23 61.85,39.13 61.85,42.8 62.36,43.31 92.58,43.31 92.71,43.18 XIOH.12
PA5
  Top 0.203: IC3.73 60.02,33.35 60.45,33.78 60.45,36.97 62.36,38.88 62.36,42.29 62.87,42.8 91.57,42.8 92.46,41.91 95.25,41.91 XIOH.11
PA6
  Top 0.203: IC3.72 60.28,32.85 60.96,33.53 60.96,36.72 62.87,38.62 62.87,41.91 63.25,42.29 90.81,42.29 92.46,40.64 XIOH.10
PA7
  Top 0.203: IC3.71 60.54,32.35 61.47,33.27 61.47,36.47 63.37,38.37 63.37,41.4 63.75,41.78 90.04,41.78 92.46,39.37 95.25,39.37 XIOH.9
PB0_SS  (via drill 0.41)
  Top 0.203: v45.47,25.91 44.88,25.35 IC3.19 41.46,25.35 41.27,25.53 38.99,25.53 38.61,25.15 37.59,25.15 v37.47,25.02 | v49.53,11.56 50.04,11.56 50.29,11.81 92.33,11.81 92.71,11.43 95.25,11.43 XIOL.1 | v33.02,25.15 32.65,25.54 R7.3
  Bottom 0.203: v45.47,25.91 45.47,25.4 48.64,22.1 48.64,12.32 v49.53,11.56 | v37.47,25.02 33.15,25.02 v33.02,25.15
PB1_SCK  (via drill 0.41)
  Top 0.203: IC3.20 40.43,24.85 v40.51,24.77 | XIOL.2 92.71,10.16 91.57,11.3 75.18,11.3 74.8,10.92 v73.91,10.92 73.53,11.3 50.67,11.3 49.66,10.29 v49.48,10.29
  Top 0.254: IC6.2 26.16,17.78 26.92,18.54 32.26,18.54 32.51,18.29 34.16,18.29 v34.42,18.54
  Bottom 0.203: v40.51,24.77 41.53,24.77 41.91,25.15 44.96,25.15 48.13,21.97 48.13,11.56 49.28,10.41 v49.48,10.29 | 63.75,27.94 64.69,27 64.69,18.31 67,16
  Bottom 0.254: 63.75,27.94 ICSP.3 | v40.51,24.77 39.12,24.77 37.97,23.62 35.69,23.62 35.18,23.11 35.18,19.3 v34.42,18.54
  Bottom 0.305: 67,16 68.83,16 v73.91,10.92
PB2_MOSI  (via drill 0.41)
  Top 0.203: IC3.21 41.31,24.35 40.97,24 v39.5,24 | XIOL.3 97.79,11.43 97.79,9.53 97.16,8.89 92.71,8.89 90.81,10.79 77.47,10.79 76.83,10.16 v75.82,10.16 75.69,10.03 73.66,10.03 72.9,10.79 51.47,10.79 v50.8,10.12
  Top 0.254: IC9.2 26.04,13.97 26.16,14.1 26.16,15.11 27.3,16.26 27.3,17.78 27.56,18.03 32,18.03 32.38,17.65 34.92,17.65 v35.18,17.53
  Bottom 0.203: v39.5,24 41.66,24 42.29,24.64 44.83,24.64 47.62,21.72 47.62,10.92 49.15,9.4 50.07,9.4 v50.8,10.12
  Bottom 0.254: 74.8,12.45 75.82,11.3 v75.82,10.16 | 67.49,17.27 65.66,19.11 65.66,23.11 67.31,24.77 67.31,27.05 66.42,27.94 ICSP.4 | v39.5,24 38.61,23.11 36.07,23.11 35.69,22.73 35.69,18.03 v35.18,17.53
  Bottom 0.305: 67.49,17.27 69.98,17.27 74.8,12.45
PB3_MISO  (via drill 0.41)
  Top 0.203: v44.58,23.62 44.35,23.85 IC3.22 41.55,23.85 40.95,23.24 37.97,23.24 36.45,24.77 v36.45,25.78 | v81.03,8.76 81.03,9.14 80.26,9.91 77.6,9.91 77.09,9.4 73.53,9.4 72.59,10.34 52.38,10.34 50.67,8.64 v50.42,8.64 | v31.37,24.26 30.73,23.6 27.05,23.6 v26.54,23.11 | U7A.15 16.13,24.52 16.13,25.27 15.75,25.65 15.24,25.65 v14.73,25.15
  Bottom 0.203: v81.03,8.76 81.15,8.76 82.93,6.99 89.66,6.99 91.19,5.46 96.9,5.46 98.3,6.86 98.3,10.29 97.16,11.43 95.25,11.43 XIOL.4 | v44.58,23.62 44.96,23.62 47.12,21.46 47.12,10.79 49.28,8.64 v50.42,8.64 | ICSP.1 65.1,29.01 65.1,18.72 67.18,16.64 | v36.45,25.78 36.32,25.91 32.13,25.91 31.37,25.15 v31.37,24.26 | v14.73,25.15 15.75,24.13 19.05,24.13 20.07,25.15 21.84,25.15 23.88,23.11 v26.54,23.11
  Bottom 0.254: v81.03,8.76 81.03,9.27 80.52,9.78 77.98,9.78 77.34,9.14 75.56,9.14 74.93,9.78 74.93,11.18 74.17,11.94 | 69.47,16.64 67.18,16.64
  Bottom 0.305: 74.17,11.94 69.47,16.64
PB4
  Top 0.203: IC3.23 42.9,23.35 42.93,23.37 41.76,23.37 41.25,22.86 37.59,22.86 35.69,24.77 35.69,48.51 36.58,49.4 PWMH.3
PB5
  Top 0.203: IC3.24 41.97,22.85 41.48,22.35 37.34,22.35 35.18,24.51 35.18,48.13 34.04,49.28 PWMH.4
PB6
  Top 0.203: IC3.25 42.92,22.35 42.93,22.35 42.16,22.35 41.66,21.84 37.08,21.84 34.67,24.26 34.67,47.24 31.75,50.16 PWMH.5
PB7  (via drill 0.41)
  Top 0.203: IC3.26 44.22,20.34 43.71,19.84 34.57,19.84 v34.29,20.19 | PWMH.6 28.96,50.29 30.23,49.02 32.13,49.02 34.16,46.99 v34.16,23.11
  Top 0.254: v13.59,46.48 10.79,46.48 10.36,46.92 IC1.3
  Bottom 0.203: v34.29,20.19 34.29,22.48 34.16,22.61 v34.16,23.11
  Bottom 0.254: PWMH.6 28.96,49.28 28.07,48.39 22.61,48.39 22.35,48.64 14.86,48.64 13.59,47.37 v13.59,46.48
PC0
  Top 0.203: IC3.53 61.49,23.35 62.74,22.1 81.53,22.1 88.65,29.21 95.25,29.21 XIOH.1
PC1
  Top 0.203: IC3.54 61.75,23.85 62.87,22.61 80.9,22.61 88.77,30.48 XIOH.2
PC2
  Top 0.203: IC3.55 62.01,24.35 63.12,23.24 68.33,23.24 70.1,25.02 82.17,25.02 88.9,31.75 95.25,31.75 XIOH.3
PC3
  Top 0.203: IC3.56 62.28,24.85 63.37,23.75 68.2,23.75 69.98,25.53 81.53,25.53 89.03,33.02 XIOH.4
PC4
  Top 0.203: IC3.57 61.92,25.35 63.04,26.47 67.36,26.47 69.98,29.08 83.95,29.08 89.15,34.29 95.25,34.29 XIOH.5
PC5
  Top 0.203: IC3.58 61.66,25.85 62.69,26.87 67,26.87 69.85,29.72 83.57,29.72 89.41,35.56 XIOH.6
PC6
  Top 0.203: IC3.59 61.52,26.35 62.48,27.3 62.48,28.7 62.79,29.01 68.28,29.01 69.62,30.35 83.19,30.35 89.66,36.83 95.25,36.83 XIOH.7
PC7
  Top 0.203: IC3.60 61.39,26.85 61.98,27.43 61.98,28.83 62.56,29.41 67.87,29.41 69.32,30.86 82.68,30.86 89.92,38.1 XIOH.8
PD7
  Top 0.203: XIOL.16 88.52,27.94 82.17,21.59 60.3,21.59 60.3,21.57 59.69,20.95 59.69,20.57 58.17,19.05 58.04,19.05 57.4,18.41 56.9,18.41 56.8,18.51 IC3.50
PE0  (via drill 0.41)
  Top 0.203: PWML.1 61.47,48.77 59.69,48.77 58.04,47.12 52.83,47.12 51.18,45.47 45.59,45.47 44.58,44.45 41.91,44.45 40.89,43.43 40.89,36.58 v41.15,36.32 41.15,35.94 42.16,34.92 43.69,34.92 43.94,34.67 43.94,34.04 43.75,33.85 IC3.2
  Top 0.254: RN5.2 28.63,31.11 28.96,31.11 30.86,33.02 30.86,34.67 v31.62,35.43
  Bottom 0.254: v31.62,35.43 39.5,35.43 40.39,36.32 v41.15,36.32
PE1  (via drill 0.41)
  Top 0.203: v40.64,35.05 40.39,35.43 40.39,43.56 41.91,45.09 44.45,45.09 45.34,45.97 50.8,45.97 52.45,47.62 57.78,47.62 59.44,49.28 60.96,49.28 PWML.2 | v40.64,33.27 40.51,33.27 40.71,33.35 IC3.3
  Top 0.254: RN5.1 29.03,30.3 31.88,33.15 v31.88,34.04
  Bottom 0.254: v40.64,35.05 v40.64,33.27 39.12,34.8 32.77,34.8 32,34.04 v31.88,34.04
PE3  (via drill 0.41)
  Top 0.203: IC3.5 40.17,32.35 39.24,33.27 39.24,43.69 41.91,46.35 44.2,46.35 45.09,47.24 49.28,47.24 v49.4,47.37
  Bottom 0.203: v49.4,47.37 49.4,47.62 50.8,49.02 PWML.6
PE4
  Top 0.203: IC3.6 39.91,31.85 38.73,33.02 38.73,43.81 41.91,46.99 43.94,46.99 44.7,47.75 46.99,47.75 47.37,48.13 57.28,48.13 58.42,49.28 PWML.3
PE5
  Top 0.203: IC3.7 42.78,31.35 42.55,31.37 39.75,31.37 38.23,32.89 38.23,43.94 41.91,47.62 43.94,47.62 44.58,48.26 46.61,48.26 46.99,48.64 55.37,48.64 55.88,49.15 PWML.4
PE6  (via drill 0.41)
  Top 0.203: 38.5,31.35 v38.48,31.37 39,30.85 IC3.8 | v32.51,29.46 31.58,29.46 R8.3
  Bottom 0.203: v38.48,31.37 36.96,31.37 34.8,29.21 32.77,29.21 v32.51,29.46
PG0  (via drill 0.41)
  Top 0.203: IC3.51 58.8,21.84 v59.05,21.46 | XIOL.13 95.25,24.13 88.14,24.13 84.07,20.07 71.75,20.07 71.25,19.56 70.36,18.67 70.1,18.41 59.69,18.41 59.44,18.67 v59.05,18.67
  Bottom 0.203: v59.05,18.67 v59.05,21.46
PG1  (via drill 0.41)
  Top 0.203: IC3.52 60.44,22.85 v60.83,22.48 | XIOL.14 88.27,25.4 83.44,20.57 71.12,20.57 69.6,19.05 60.33,19.05 59.94,19.43 v59.94,19.56
  Bottom 0.203: v59.94,19.56 60.58,19.56 61.34,20.32 61.34,21.97 v60.83,22.48
PG2  (via drill 0.41)
  Top 0.203: IC3.70 59.8,31.85 59.92,31.73 59.92,29.49 v60.33,29.08 | v60.58,20.7 61.09,20.7 61.47,21.08 82.8,21.08 88.39,26.67 95.25,26.67 XIOL.15
  Bottom 0.203: v60.58,20.7 60.2,20.7 59.94,20.95 59.94,28.57 v60.33,29.08
PG5  (via drill 0.41)
  Top 0.203: IC3.1 42.73,34.35 42.67,34.29 40.13,34.29 39.75,34.67 39.75,43.56 41.91,45.72 44.32,45.72 45.09,46.48 50.04,46.48 v50.67,47.12
  Bottom 0.203: PWML.5 53.34,49.78 v50.67,47.12
PH3
  Top 0.203: IC3.15 38.31,27.35 37.72,27.94 37.72,44.07 41.91,48.26 43.81,48.26 44.32,48.77 46.23,48.77 PWML.7
PH4  (via drill 0.41)
  Top 0.203: PWML.8 45.47,50.8 43.56,48.9 41.91,48.9 37.21,44.2 37.21,27.69 38.05,26.85 IC3.16 44.53,26.85 v44.58,26.8 | R4.1 29.86,21.84 30.86,21.84 v31.5,21.21
  Bottom 0.203: v31.5,21.21 31.24,21.46 31.24,22.86 32.51,24.13 37.72,24.13 39.37,25.78 43.56,25.78 v44.58,26.8
PH5
  Top 0.203: IC3.17 37.79,26.35 36.7,27.43 36.7,45.59 40.01,48.9 40.64,48.9 41.66,49.91 PWMH.1
PH6
  Top 0.203: IC3.18 42.73,25.85 42.67,25.91 37.47,25.91 36.2,27.18 36.2,46.1 39.12,49.02 PWMH.2
PH7  (via drill 0.41)
  Top 0.203: v32.13,22.48 31.41,22.94 R7.1 | v33.4,19.3 44.2,19.3 44.45,19.05 45.09,19.05 45.3,19.27 IC3.27
  Bottom 0.203: v32.13,22.48 33.15,21.46 33.15,19.56 v33.4,19.3
PJ2
  Top 0.203: IC3.65 57.14,29.35 56.52,29.97 56.52,31.37 56.13,31.75 55.24,31.75 54.36,30.86 54.36,25.15 52.45,23.24 47.62,23.24 45.97,21.59 44.7,21.59 43.43,20.32 36.07,20.32 35.31,21.08 33.91,21.08 32.09,19.26 R4.3
PJ6
  Top 0.203: IC3.69 57.68,31.35 57.53,31.5 57.53,31.62 56.39,32.77 54.99,32.77 53.34,31.11 53.34,25.53 52.07,24.26 47.37,24.26 45.72,22.61 44.45,22.61 43.18,21.34 36.58,21.34 35.69,22.23 33.78,22.23 33.4,22.61 33.4,24.26 33.78,24.64 33.78,25.53 32.64,26.67 31.64,26.67 R8.1
PL0
  Top 0.203: 49.28,20.3 49.28,17.91 54.86,12.32 90.3,12.32 91.95,13.97 95.25,13.97 XIOL.5
  Top 0.254: IC3.35 49.3,20.32 49.28,20.3
PL1
  Top 0.203: IC3.36 49.8,18.02 54.99,12.83 89.53,12.83 91.95,15.24 XIOL.6
PL2
  Top 0.203: 50.29,20.3 50.29,18.16 55.12,13.34 88.9,13.34 92.08,16.51 95.25,16.51 XIOL.7
  Top 0.254: IC3.37 50.27,20.32 50.29,20.3
PL3
  Top 0.203: IC3.38 50.8,18.29 55.24,13.84 88.27,13.84 92.2,17.78 XIOL.8
PL4
  Top 0.203: 51.31,20.22 51.31,18.41 55.37,14.35 87.63,14.35 92.33,19.05 95.25,19.05 XIOL.9
  Top 0.254: IC3.39 51.3,20.28 51.33,20.24 51.31,20.22
PL5
  Top 0.203: IC3.40 51.8,18.56 55.5,14.86 87,14.86 92.46,20.32 XIOL.10
PL6
  Top 0.203: 52.32,20.24 52.32,18.67 55.63,15.37 86.49,15.37 92.71,21.59 95.25,21.59 XIOL.11
  Top 0.254: IC3.41 52.3,20.32 52.27,20.3 52.32,20.24
PL7
  Top 0.203: IC3.42 52.8,18.83 55.75,15.88 85.72,15.88 92.71,22.86 XIOL.12
RD+
  Top 0.254: RN4.4 13.4,39.3 13.97,38.74 IC4.29
RD-
  Top 0.254: RN4.1 12.77,36.87
  Top 0.305: IC4.30 15,38.24 13.66,36.9 RN4.1
RESET  (via drill 0.41)
  Top 0.254: 64.72,24.31 68.12,24.31 69.85,26.04 78.74,26.04 v80.01,27.3 | 46.8,18.94 45.47,17.6 45.47,16.38 46.86,14.99 RESET-EN.1 RESET-EN.2 | POWER.1 33.02,1.65 34.04,0.64 46.61,0.64 47.37,1.4 47.37,7.24 v47.43,7.3 | RESET.3 77.72,23.74 v78.87,23.75
  Top 0.305: 46.8,18.94 IC3.30 | ICSP.5 64.72,24.31 | RN1.1 79.97,39.08 80.9,40.01 82.55,40.01 82.68,40.13 84.2,40.13 84.45,39.88 84.45,33.78 82.8,32.13 v80.01,32.13 RESET.4 | v78.61,8.76 78.49,8.64 73.28,8.64 72.08,9.83 52.81,9.83 50.55,7.62 v50.04,7.11 | RESET-EN.2 C10.2 | RESET-EN.1 46.74,13.46 46.74,12.95 C1.1 47.75,11.68 47.75,7.62 v47.43,7.3
  Bottom 0.254: 63.75,25.27 64.14,24.89 64.14,17.91 66.67,15.37 | v78.87,23.75 78.87,25.27 79.5,25.91 79.5,26.8 v80.01,27.3
  Bottom 0.305: v78.61,8.76 78.11,8.76 77.98,8.64 74.93,8.64 68.2,15.37 66.67,15.37 | 63.75,25.27 ICSP.5 | v80.01,27.3 v80.01,32.13 | v50.04,7.11 47.62,7.11 v47.43,7.3
RESET2
  Top 0.203: RN3.8 8.19,48.95 8.31,49.07 10.97,49.07 11.94,49.91 12.83,49.91 13.46,49.28 13.46,48.9 14.35,48.01 14.61,48.01 15.11,47.5 ICSP1.5
  Top 0.305: IC4.24 17.17,43.91 17.02,44.07 17.02,46.23 ICSP1.5
RST_3V3  (via drill 0.41)
  Top 0.254: IC5.4 23.1,20.97 22.5,21.57 v22.5,23.11 | v20.45,24.26 20.32,24.26 19.3,23.24 18.03,23.24 17.65,23.63 U7A.12
  Bottom 0.254: v20.45,24.26 21.36,24.26 v22.5,23.11
RST_5V
  Top 0.203: RN6.4 26.6,26.61 | 27.3,24.89 30.61,24.89 30.86,25.15 31.75,25.15 32,24.89 33.02,23.75 33.02,21.59 31.75,20.32 30.24,20.32 R4.2 29.48,20.56 28.7,21.34 28.45,21.34 27.81,21.97 26.54,21.97 26.16,21.59 26.16,20.57 25.91,20.32 IC5.2
  Top 0.254: 27.3,24.89 26.67,25.53 26.67,25.65 26.6,25.72 RN6.4
RXD1  (via drill 0.41)
  Top 0.203: IC3.45 54.33,20.35 54.36,20.32 54.36,19.18 56.19,17.35 71.96,17.35 v72.64,17.91
  Bottom 0.203: COMMUNICATION.3 81.28,42.67 74.04,35.43 74.04,19.3 v72.64,17.91
RXD2  (via drill 0.41)
  Top 0.203: IC3.12 41.04,28.85 v41.02,28.57
  Bottom 0.203: v41.02,28.57 41.02,29.34 43.05,31.37 43.05,37.47 43.43,37.85 43.43,38.99 42.67,39.75 42.67,44.83 43.05,45.21 51.18,45.21 51.94,45.97 55.63,45.97 56.26,45.34 60.45,45.34 63.5,48.39 63.96,48.39 64.85,49.28 67.13,49.28 68.28,48.13 75.06,48.13 76.2,49.28 COMMUNICATION.5
RXD3  (via drill 0.41)
  Top 0.203: COMMUNICATION.7 71.12,49.53 70.36,48.77 67.69,48.77 66.8,47.75 v66.8,47.37 | v55.24,29.59 55.63,29.59 56.9,28.32 58.8,28.32 IC3.63
  Bottom 0.203: v66.8,47.37 66.8,46.99 55.7,35.76 55.7,32.05 56.52,31.24 56.52,30.23 55.88,29.59 v55.24,29.59
RXL
  Top 0.254: IC4.10 21.82,37.74 25.27,34.29 RX.C
SCK2
  Top 0.254: ICSP1.3 19.56,48.77 21.59,48.77 22.86,47.5 22.86,42.04 21.97,41.15 21.97,40.39 21.85,40.26 IC4.15
SCK_3V3
  Top 0.254: U7A.13 17.15,25.4 17.4,25.65 20.83,25.65 21.72,24.89 21.72,21.46 22.73,20.45 22.73,18.67 22.99,18.41 23.39,18.41 IC6.4
SCL  (via drill 0.41)
  Top 0.203: IC3.43 53.3,18.96 55.88,16.38 74.68,16.38 75.06,16.76 v75.31,16.89
  Top 0.254: 80.54,37.23 80.64,37.34 80.64,38.86
  Top 0.305: v81.41,39.12 80.9,39.12 80.64,38.86 | 80.54,37.23 RN1.2
  Bottom 0.203: v75.31,16.89 75.31,34.42 80.01,39.12 v81.41,39.12 81.41,40.77 82.55,41.91 82.55,46.1 86.36,49.91 COMMUNICATION.1
SDA  (via drill 0.41)
  Top 0.203: v74.04,17.65 73.28,16.89 56.01,16.89 53.85,19.05 53.85,19.94 53.8,20.04 53.8,20.14 IC3.44
  Top 0.305: v78.74,38.99 78.74,36.83 79.12,36.45 79.95,36.45 RN1.3
  Bottom 0.203: COMMUNICATION.2 83.82,49.28 81.92,47.37 81.92,42.16 v78.74,38.99 74.68,34.92 74.68,18.29 v74.04,17.65
SS_3V3
  Top 0.254: U7A.14 16.65,25.79 17.02,26.16 21.59,26.16 22.97,24.78 IC8.4
SS_MAX5
  Top 0.203: R7.2 27.32,24.24 27.18,24.26
  Top 0.254: RN6.2 25,26.31 26.29,25.02 26.29,24.13 | 27.18,24.26 27.05,24.13 26.29,24.13 | IC8.2 26.29,24.13
SW
  pour Top (no thermals): 34.29,14.22 36.2,14.22 36.2,17.4 38.73,17.4 38.73,12.45 37.72,11.43 32.38,11.43 32.38,12.95 34.29,12.95
TXD1  (via drill 0.41)
  Top 0.203: IC3.46 54.8,20.26 54.86,20.19 54.86,19.3 56.26,17.91 70.74,17.91 v72.01,19.18
  Bottom 0.203: COMMUNICATION.4 78.74,42.67 73.41,37.34 73.41,19.94 72.64,19.18 v72.01,19.18
TXD2  (via drill 0.41)
  Top 0.203: IC3.13 41.94,28.35 41.4,27.81 40.01,27.81 39.75,28.07 v39.75,28.57
  Bottom 0.203: v39.75,28.57 39.75,28.96 42.55,31.75 42.55,37.59 42.93,37.97 42.93,38.86 42.16,39.62 42.16,45.09 42.8,45.72 51.05,45.72 51.94,46.61 55.88,46.61 56.52,45.97 60.45,45.97 63.37,48.9 63.88,48.9 64.77,49.78 67.21,49.78 68.35,48.64 72.77,48.64 73.66,49.53 COMMUNICATION.6
TXD3  (via drill 0.41)
  Top 0.203: COMMUNICATION.8 68.33,50.8 66.42,48.9 66.42,48.51 v65.28,47.37 | IC3.64 58.66,28.85 58.55,28.83 57.02,28.83 56.01,29.84 56.01,30.48 v55.63,30.86
  Bottom 0.203: v65.28,47.37 65.28,46.23 55.22,36.14 55.22,31.27 v55.63,30.86
TXL
  Top 0.254: 26.8,36.83 TX.C 26.76,36.7 23.62,36.7 22.09,38.24 IC4.11
UGND
  Top 0.305: IC4.28 14.74,39.24 14.35,39.62
  Top 0.61: L2.1 9.14,45.21 10.79,43.56 11.01,43.56 C16.2 11.18,42.65 11.73,42.09 13.89,42.09 14.35,41.63 14.35,39.62
  Top 0.813: X2.4 6.5,36.83 5.08,36.83 4.45,37.47 4.45,39.75 8.13,43.43 8.13,45.17 L2.1
  Bottom 0.813: X2.4 6.52,36.53 GROUND.1
USBVCC  (via drill 0.41)
  Top 0.305: IC4.31 15.39,37.74 14.61,36.96
  Top 0.406: 14.61,34.92 14.61,36.96
  Top 0.508: v3.05,49.53 F1.1 3.12,51.28 T1.1 | v9.65,30.99 9.91,30.99 9.91,32.38 10.41,32.89 C11.1 12.06,33.4 12.83,34.16 13.84,34.16 14.61,34.92
  Bottom 0.508: v3.05,49.53 3.05,46.86 1.52,45.34 1.52,41.91 3.56,39.88 3.56,38.23 1.52,36.2 1.52,27.43 2.54,26.42 5.08,26.42 v9.65,30.99
USHIELD  (via drill 0.41)
  Top 0.61: 4.06,24.77 4.14,24.49 8.59,24.49 9.02,24.89 11.05,24.89 11.56,24.38 11.56,23.64 Z4.1 | Z3.1 11.54,17.89 10.67,17.02 5.17,17.02 PHONE.SG2
  Top 0.813: Z2.1 10.18,41.26 10.05,41.26 9.65,41.66 v9.65,42.67 | L2.2 4.92,45.21 X2.P$1 | 3.81,33.02 5.08,33.02 5.71,33.66 6.99,33.66 8.64,35.31 Z1.1 | Z3.1 11.56,18.27
  Top 1.27: 3.81,33.02 X2.P$2 3.81,30.48 4.06,30.23 PHONE.SG1 4.06,24.77 PHONE.SG2
  Bottom 0.813: v9.65,42.67 5.49,42.67 X2.P$1
  Bottom 1.27: X2.P$2 3.81,33.91 4.83,34.92 4.83,40.89 3.81,41.91 X2.P$1
VIN  (via drill 0.41)
  Top 0.203: RN3.6 6.99,47.35 6.73,47.1 6.73,46.1 7.11,45.72 7.11,43.69 v2.41,39.12
  Top 0.305: v2.79,11.43 9.26,11.43 11.68,9 X1.2
  Top 0.406: IC2.5 31.62,11.3 31.24,10.92 30,10.92 C4.+
  Top 0.61: R1.1 27.46,8.64 C4.+
  Top 0.813: R1.1 26.04,8.13 26.04,8 24.51,6.48 19.99,6.48 19.96,6.5 v19.56,6.1 | X1.2 13.07,9.69 17.65,9.69 | D2.C 19.26,5.8 v19.56,6.1 | 17.65,9.69 20.05,9.69 PC1.+ 20.57,8.99 20.57,7.11 v19.56,6.1 | 17.65,9.69 C3.1
  Bottom 0.203: v2.41,39.12 0.89,37.59 0.89,13.34 v2.79,11.43
  Bottom 1.016: POWER.6 45.72,4.57 43.81,6.48 31.62,6.48 29.84,4.7 20.95,4.7 v19.56,6.1
VUCAP
  Top 0.305: C16.1 13.17,43.43 13.72,43.43 15.11,42.04 15.11,40.13 15.51,39.74 IC4.27
XT1
  Top 0.305: IC4.1 17.17,35.21 17.02,35.05 17.02,33.44 Y2.1 16.52,33.53 15.88,32.89 C13.1
XT2  (1 unrouted)
  Top 0.203: 17.91,32.26 17.91,34.54
  Top 0.305: IC4.2 17.67,34.82 17.91,34.54 | 17.91,32.26 18.8,31.37 | C12.1 18.95,31.11 Y2.3
XTAL1
  Top 0.203: Y1.3 50.8,14.24 50.8,15.49 48.8,17.49 IC3.34
XTAL2
  Top 0.203: IC3.33 48.3,17.02 48.78,16.61 Y1.1
XVCC
  Top 0.508: X2.1 6.85,35.18 3.94,35.18 1.4,37.72 1.4,46.48 2.5,47.58 F1.2

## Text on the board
Top: HMEGA_Rev2 | ARDUINO MEGA2560 ADK (for Android) | Reference Designs ARE PROVIDED "AS IS" AND "WITH ALL FAULTS. Arduino DISCLAIMS ALL OTHER WARRANTIES, EXPRESS OR IMPLIED, | REGARDING PRODUCTS, INCLUDING BUT NOT LIMITED TO, ANY IMPLIED WARRANTIES OF MERCHANTABILITY OR FITNESS FOR A PARTICULAR PURPOSE | Arduino may make changes to specifications and product descriptions at any time, without notice. The Customer must not | rely on the absence or characteristics of any features or instructions marked "reserved" or "undefined." Arduino reserves | these for future definition and shall have no responsibility whatsoever for conflicts or incompatibilities arising from future changes to them. | The product information on the Web Site or Materials is subject to change without notice. Do not finalize a design with this information. | ARDUINO is a registered trademark. | Android is a trademark of Google Inc. Use of this trademark is subject to Google Permissions
tNames: M.Banzi | 5V | D.Cuartielles | T.Igoe | G.Martino | 9 | 8 | 7 | 6 | 5 | 4 | 3 | 2 | 1 | 0 | 22 | 14 | 15 | 16 | 17 | 18 | 19 | 20 | 21 | D.Mellis | 13 | 12 | 11 | 10 | GND | 24 | AREF | PWM | 26 | TX | RX | TX3 | RX3 | TX2 | RX2 | TX1 | RX1 | SDA | SCL | 28 | 30 | 31 | 32 | 33 | MADE IN | 34 | 35 | 1 | 36 | 37 | 38 | 39 | 40 | 41 | ITALY | DIGITAL | 42 | 43 | www.arduino.cc | 44 | 45 | 46 | 47 | TM | 48 | 49 | Arduino | MISO | MOSI | MEGA 2560 ADK | TM | SCK | SS | for Android | ANALOG IN | 0 | 1 | 2 | 3 | 4 | 5 | 6 | 7 | 8 | 9 | 10 | 11 | 12 | 13 | 14 | 15 | GND | RESET | 3V3 | 5V | GND | GND | VIN
bNames: MADE IN | designed by | ITALY | tinker it
ReferenceLC: PC1 | PC2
